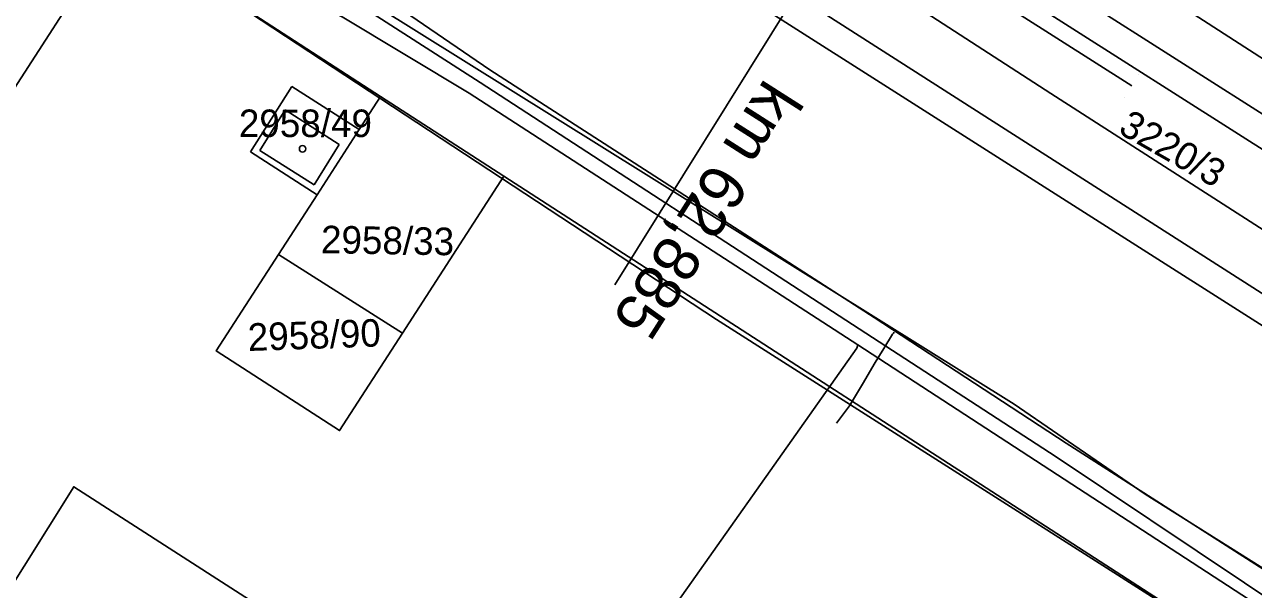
# Model space of a CAD drawing. Extents: x -621145 to -620110, y -1122807 to -1121971.
# Drawn here: x -620783.5 to -620716.5, y -1122450.2 to -1122419.4 of the extents above; entities that cross this region are included whole.
import ezdxf

# ---------------------------------------------------------------- set-up
doc = ezdxf.new("R2010")
doc.units = 0
for name, color, linetype in [('CETIN', 7, 'Continuous'), ('GasNet', 7, 'Continuous'), ('itself', 7, 'Continuous'), ('SEE', 7, 'Continuous'), ('SSZT', 7, 'Continuous'), ('VAS stoka', 7, 'Continuous'), ('VAS vodovod', 7, 'Continuous'), ('Vrstva 1', 7, 'Continuous'), ('Vrstva 53', 7, 'Continuous'), ('Vrstva 55', 7, 'Continuous'), ('Vrstva 56', 7, 'Continuous'), ('Vrstva 57', 7, 'Continuous'), ('Vrstva 6', 7, 'Continuous'), ('Vrstva 62', 7, 'Continuous')]:
    doc.layers.add(name, color=color, linetype=linetype)

msp = doc.modelspace()

# ---------------------------------------------------------------- linework, layer by layer
at = {"layer": 'CETIN'}
msp.add_lwpolyline([(-620825.92, -1122405.87), (-620824.51, -1122406.99), (-620818.94, -1122399.06), (-620813.77, -1122391.56), (-620811.94, -1122388.94), (-620806.05, -1122392.88), (-620797.93, -1122398.39), (-620788.82, -1122404.57), (-620785.51, -1122405.86), (-620781.04, -1122408.44), (-620779.59, -1122408.85), (-620776.1, -1122410.97), (-620774.86, -1122411.81), (-620766.93, -1122416.76), (-620729.54, -1122440.11), (-620722.4, -1122445), (-620713.88, -1122450.37)], dxfattribs=at)
at = {"layer": 'GasNet'}
msp.add_lwpolyline([(-620782.63, -1122409.86), (-620782.01, -1122410.24), (-620780.25, -1122411.07), (-620777.02, -1122412.94), (-620768.84, -1122416.49), (-620765.93, -1122417.88), (-620758.63, -1122422.59), (-620737.62, -1122436.24), (-620727.26, -1122442.97), (-620706.73, -1122456.7), (-620700.22, -1122460.96), (-620682.51, -1122472.52), (-620658.5, -1122488), (-620649.67, -1122493.31), (-620649.45, -1122493.45), (-620648.52, -1122494.04), (-620647.09, -1122494.92), (-620646.9, -1122495.04), (-620639.06, -1122500.54), (-620610.88, -1122519.2)], dxfattribs=at)
at = {"layer": 'itself'}
msp.add_lwpolyline([(-620721.666, -1122450.842), (-620745.766, -1122435.492), (-620776.456, -1122415.302), (-620776.396, -1122414.332), (-620775.686, -1122413.162), (-620774.756, -1122411.292), (-620776.986, -1122409.872), (-620778.946, -1122408.642), (-620781.216, -1122407.102), (-620786.306, -1122404.212), (-620792.996, -1122399.612), (-620794.806, -1122398.032), (-620806.306, -1122390.882), (-620816.806, -1122384.122), (-620818.796, -1122383.362), (-620822.246, -1122382.502), (-620843.096, -1122368.972), (-620871.286, -1122351.222), (-620896.976, -1122334.702), (-620917.616, -1122321.732), (-620932.526, -1122311.532), (-620939.766, -1122306.092)], dxfattribs=at)
at = {"layer": 'SEE'}
msp.add_lwpolyline([(-620611.375, -1122497.696), (-620665.569, -1122462.755), (-620686.035, -1122449.829), (-620727.537, -1122423.183), (-620794.508, -1122379.862), (-620815.52, -1122356.954), (-620832.168, -1122344.663), (-620847.808, -1122332.592), (-620908.257, -1122294.686)], dxfattribs=at)
at = {"layer": 'SSZT'}
msp.add_lwpolyline([(-620879.238, -1122313.316), (-620842.993, -1122336.61), (-620835.049, -1122343.251), (-620812.66, -1122358.949), (-620764.902, -1122389.752), (-620688.594, -1122438.969), (-620596.981, -1122496.725), (-620576.744, -1122509.484), (-620506.746, -1122556.123), (-620447.293, -1122593.619), (-620363.271, -1122647.563), (-620313.966, -1122679.218), (-620306.51, -1122669.289), (-620273.137, -1122696.274), (-620258.422, -1122709.142), (-620248.072, -1122696.094)], dxfattribs=at)
at = {"layer": 'VAS stoka'}
for points in [[(-620781.72, -1122408.87), (-620776.69, -1122412.14), (-620774.2, -1122412.02), (-620772.21, -1122412.95), (-620766.77, -1122415.95), (-620758.11, -1122421.89), (-620737.16, -1122435.39), (-620726.71, -1122442.22), (-620705.9, -1122455.54), (-620681.71, -1122471.08), (-620665.23, -1122481.83), (-620655.606, -1122488.117), (-620638.12, -1122499.53), (-620609.99, -1122517.38), (-620585.88, -1122533.44), (-620564.23, -1122548.6), (-620546.83, -1122572.05), (-620541.253, -1122582.331), (-620541.865, -1122584.423), (-620543.527, -1122584.845), (-620544.25, -1122585.029)], [(-620739.22, -1122441.14), (-620738.51, -1122440.2), (-620737.81, -1122439.02), (-620737.11, -1122437.84), (-620736.64, -1122437.07), (-620736.17, -1122436.3), (-620736.12, -1122436.245), (-620736.07, -1122436.19)]]:
    msp.add_lwpolyline(points, dxfattribs=at)
at = {"layer": 'VAS vodovod'}
for points in [[(-620783.05, -1122410.36), (-620779.49, -1122412.44), (-620776.82, -1122413.57), (-620766.15, -1122419), (-620759.23, -1122423.16), (-620738.05, -1122436.88), (-620666.7, -1122483.31), (-620630.69, -1122506.76), (-620611.44, -1122519.95), (-620587.32, -1122536.52), (-620566.14, -1122551.51), (-620558.22, -1122559.71), (-620551.85, -1122569.08), (-620547.83, -1122576.32), (-620546.15, -1122586.98), (-620546.105, -1122587.264)], [(-620738.05, -1122436.88), (-620738.12, -1122437.06), (-620750.23, -1122454.2)]]:
    msp.add_lwpolyline(points, dxfattribs=at)
at = {"layer": 'Vrstva 1'}
msp.add_lwpolyline([(-620811.348, -1122356.777), (-620801.076, -1122364.818), (-620794.028, -1122370.353), (-620788.085, -1122375.002), (-620768.881, -1122390.097), (-620768.433, -1122390.449), (-620761.754, -1122395.699), (-620755.252, -1122400.953), (-620748.862, -1122405.846), (-620748.158, -1122406.325), (-620737.324, -1122413.726), (-620723.134, -1122422.771)], dxfattribs=at)
at = {"layer": 'Vrstva 53'}
msp.add_line((-620679.51, -1122447.56), (-620741.46, -1122408.09), dxfattribs=at)
at = {"layer": 'Vrstva 55'}
for p, q in [((-620684.91, -1122455.63), (-620825.92, -1122365.89)), ((-620645.72, -1122471.03), (-620807.67, -1122367.84)), ((-620741.46, -1122408.09), (-620679.51, -1122447.56)), ((-620778.34, -1122414.11), (-620801.537, -1122450.017)), ((-620764.06, -1122423.34), (-620778.34, -1122414.11)), ((-620768.9, -1122422.81), (-620771.15, -1122426.36)), ((-620768.9, -1122422.81), (-620765.22, -1122425.14)), ((-620764.06, -1122423.34), (-620765.22, -1122425.14)), ((-620757.34, -1122427.68), (-620764.06, -1122423.34)), ((-620765.22, -1122425.14), (-620767.52, -1122428.7)), ((-620771.15, -1122426.36), (-620767.52, -1122428.7)), ((-620762.87, -1122436.24), (-620757.34, -1122427.68)), ((-620702.74, -1122462.95), (-620757.34, -1122427.68)), ((-620767.52, -1122428.7), (-620769.63, -1122431.96)), ((-620762.87, -1122436.24), (-620769.63, -1122431.96))]:
    msp.add_line(p, q, dxfattribs=at)
for points in [[(-620769.63, -1122431.96), (-620773.01, -1122437.2), (-620766.29, -1122441.54), (-620762.87, -1122436.24)], [(-620758.93, -1122466.63), (-620763.57, -1122474.01), (-620789, -1122457.71), (-620780.78, -1122444.6), (-620755.36, -1122460.94)]]:
    msp.add_lwpolyline(points, dxfattribs=at)
at = {"layer": 'Vrstva 56'}
for p, q in [((-620810.36, -1122373.73), (-620648.08, -1122477.56)), ((-620770.64, -1122426.28), (-620769.25, -1122424.08)), ((-620769.25, -1122424.08), (-620766.31, -1122425.96)), ((-620767.68, -1122428.15), (-620766.31, -1122425.96)), ((-620770.64, -1122426.28), (-620767.68, -1122428.15))]:
    msp.add_line(p, q, dxfattribs=at)
at = {"layer": 'Vrstva 57'}
msp.add_circle((-620768.31, -1122426.2), 0.175, dxfattribs=at)
at = {"layer": 'Vrstva 6'}
msp.add_line((-620737.11, -1122410.843), (-620751.294, -1122433.601), dxfattribs=at)
at = {"layer": 'Vrstva 62'}
for p, q in [((-620722.75, -1122422.156), (-620722.75, -1122422.156)), ((-620723.518, -1122423.386), (-620723.518, -1122423.386))]:
    msp.add_line(p, q, dxfattribs=at)

# ---------------------------------------------------------------- texts
at = {"layer": 'Vrstva 57'}
msp.add_text('2958/49', height=1.5, dxfattribs=at).set_placement((-620771.78, -1122425.557))
for s, rotation, p in [('3220/3', 330.3, (-620723.934, -1122425.305)), ('2958/33', 359.06085, (-620767.316, -1122431.88)), ('2958/90', 2.00952, (-620771.269, -1122437.211))]:
    msp.add_text(s, height=1.5, rotation=rotation, dxfattribs=at).set_placement(p)
at = {"layer": 'Vrstva 6'}
msp.add_text('km 62,885', height=2.5, rotation=237.48572, dxfattribs=at).set_placement((-620743.108, -1122422.29))

doc.saveas('drawing.dxf')
